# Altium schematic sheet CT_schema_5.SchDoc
size 253 x 245 mm
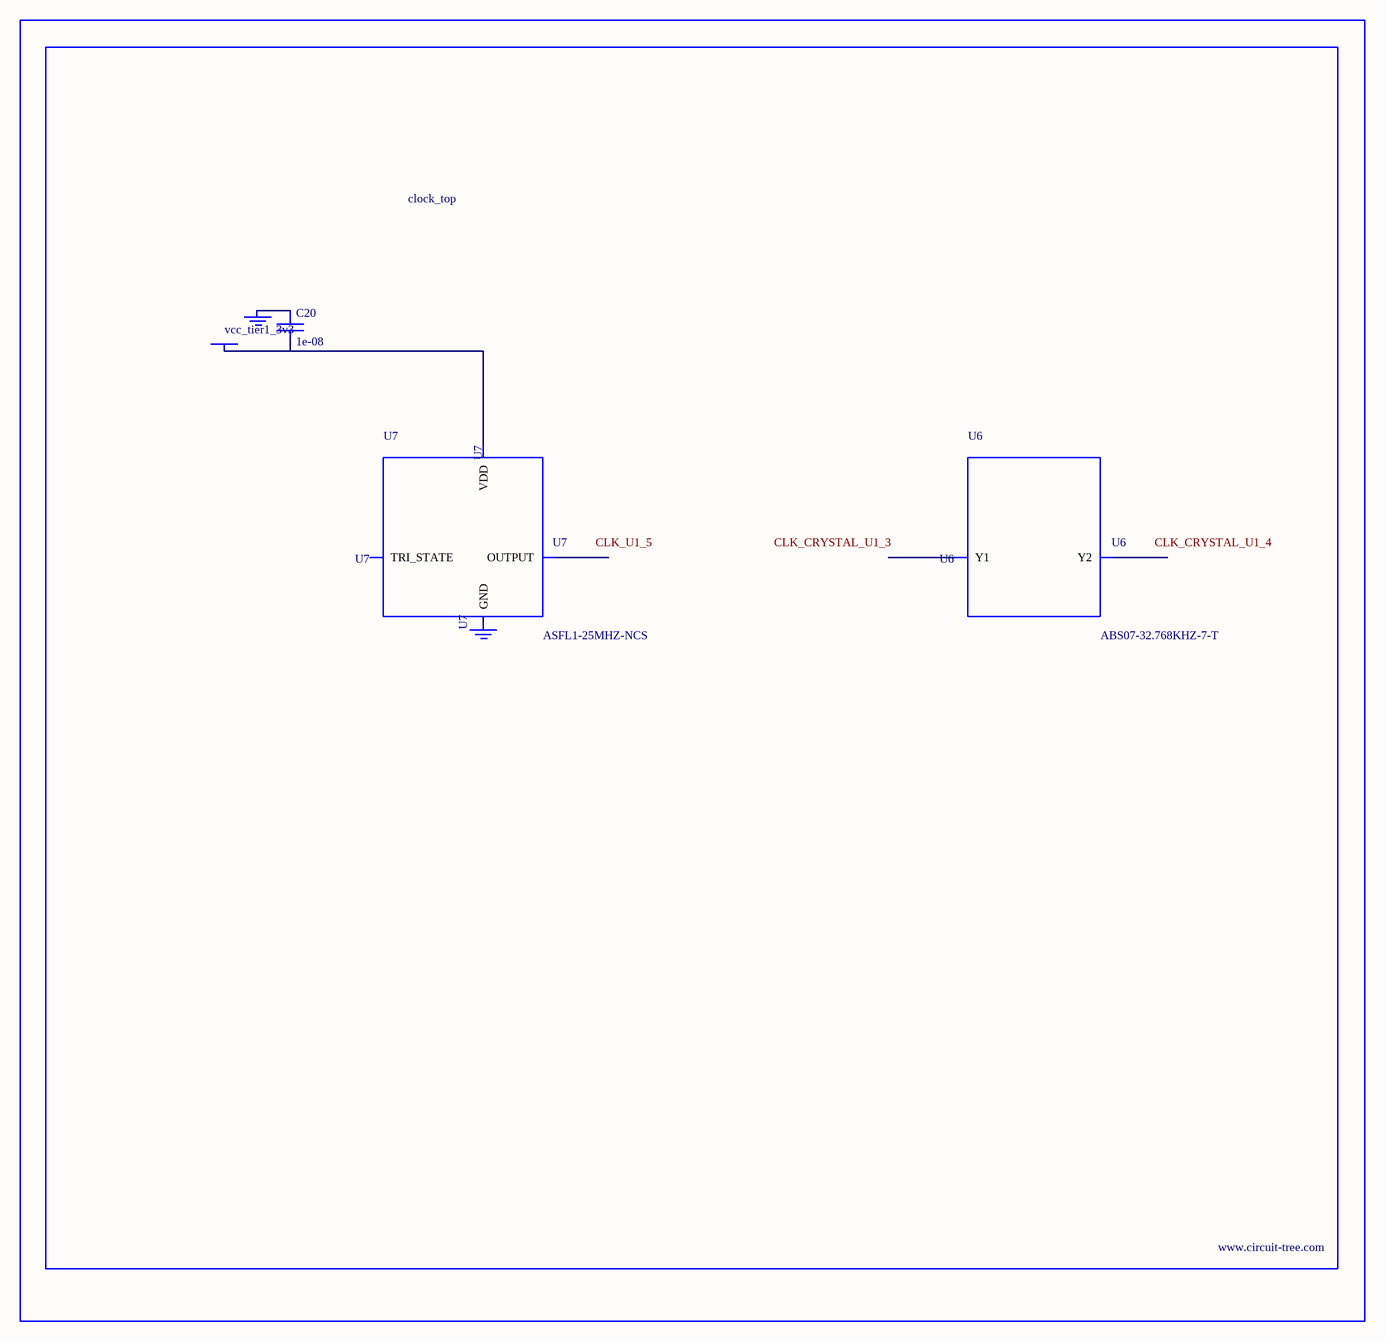
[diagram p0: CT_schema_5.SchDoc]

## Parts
BORDER4  (no value)
C20  1e-08  [C0402]
GND_INSTANCE_4_0  (no value)
GND_INSTANCE_4_1  (no value)
POWER_INSTANCE_4_0  vcc_tier1_3v3
U6  ABS07-32.768KHZ-7-T  [ABS07-32.768KHZ-7-T]
U7  ASFL1-25MHZ-NCS  [ASFL1]

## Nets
NetC20_1: C20.1 GND_INSTANCE_4_0.0(GND)
NetC20_2: C20.2 POWER_INSTANCE_4_0.0(PWR) U7.4(VDD)

Not connected (* = marked no-connect by the designer): GND_INSTANCE_4_1 0(GND); U6 1(Y1) 2(Y2); U7 1(TRI_STATE) 2(GND) 3(OUTPUT)

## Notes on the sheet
- Labels drawn without touching a wire or pin: CLK_CRYSTAL_U1_3, CLK_CRYSTAL_U1_4, CLK_U1_5

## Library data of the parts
BORDER4 = BORDER_PAGE4
C20 = C0402C103K3RAC
GND_INSTANCE_4_0 GND_INSTANCE_4_1 = GND
POWER_INSTANCE_4_0 = PWR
